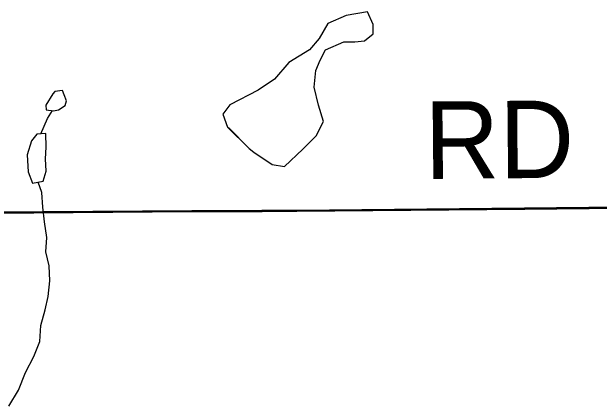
# Model space of a CAD drawing. Extents: x 0 to 34, y 0 to 22.
# Drawn here: x 24.4702 to 24.9014, y 12.5806 to 12.87 of the extents above; entities that cross this region are included whole.
import ezdxf

# ---------------------------------------------------------------- set-up
doc = ezdxf.new("R2010")
doc.units = 0
for name, color, linetype in [('GM_X_Corporation', 7, 'Continuous'), ('GM_X_County_Road', 7, 'Continuous'), ('GM_X_County_Road_Text', 7, 'Continuous'), ('GM_X_Minor_Lake', 7, 'Continuous'), ('GM_X_Minor_River', 7, 'Continuous')]:
    doc.layers.add(name, color=color, linetype=linetype)

msp = doc.modelspace()

# ---------------------------------------------------------------- linework, layer by layer
at = {"layer": 'GM_X_Corporation'}
for points in [[(25.33919, 12.72985), (25.3125, 12.72939), (25.28828, 12.729), (25.15404, 12.7277), (25.13367, 12.72762), (24.97571, 12.72705), (24.91727, 12.72656), (24.84644, 12.72583), (24.6793, 12.72429), (24.65383, 12.72414), (24.60225, 12.72396), (24.45681, 12.72289)], [(24.45681, 12.72289), (24.60225, 12.72396), (24.65383, 12.72414), (24.6793, 12.72429), (24.84644, 12.72583), (24.91727, 12.72656), (24.97571, 12.72705), (25.13367, 12.72762), (25.15404, 12.7277), (25.28828, 12.729), (25.3125, 12.72939), (25.33919, 12.72985)]]:
    msp.add_lwpolyline(points, dxfattribs=at)
at = {"layer": 'GM_X_County_Road'}
msp.add_lwpolyline([(24.33555, 12.72187), (24.36213, 12.72202), (24.3875, 12.72204), (24.40983, 12.72221), (24.4359, 12.72217), (24.45702, 12.72234), (24.60246, 12.7234), (24.65404, 12.72358), (24.6795, 12.72374), (24.84664, 12.72528), (24.91748, 12.72601), (24.97591, 12.7265), (25.13388, 12.72707)], dxfattribs=at)
at = {"layer": 'GM_X_Minor_Lake'}
for p, q in [((24.50038, 12.80986), (24.49515, 12.80148)), ((24.6285, 12.78543), (24.64452, 12.76963)), ((24.64452, 12.76963), (24.62929, 12.78507)), ((24.48143, 12.76497), (24.48214, 12.75252))]:
    msp.add_line(p, q, dxfattribs=at)
for points in [[(24.73117, 12.87003), (24.71567, 12.86725), (24.70209, 12.86146), (24.69574, 12.85042), (24.68862, 12.84202), (24.67355, 12.8328), (24.66305, 12.82059), (24.651, 12.81253), (24.63027, 12.80175), (24.62502, 12.79489), (24.6285, 12.78543)], [(24.64452, 12.76963), (24.64794, 12.767), (24.66126, 12.758), (24.67036, 12.75655), (24.68388, 12.76917), (24.69365, 12.7791), (24.69887, 12.78938), (24.69537, 12.80149), (24.69223, 12.81474), (24.69328, 12.82688), (24.69662, 12.8345), (24.70035, 12.84211), (24.71393, 12.8479), (24.72188, 12.84796), (24.72906, 12.84877), (24.73546, 12.85375), (24.7354, 12.86058), (24.73117, 12.87003), (24.71567, 12.86725), (24.70209, 12.86146), (24.69574, 12.85042), (24.68862, 12.84202), (24.67355, 12.8328), (24.66305, 12.82059), (24.651, 12.81253), (24.63027, 12.80175), (24.62502, 12.79489), (24.6285, 12.78543)], [(24.64452, 12.76963), (24.64794, 12.767), (24.66126, 12.758), (24.67036, 12.75655), (24.68388, 12.76917), (24.69365, 12.7791), (24.69887, 12.78938), (24.69537, 12.80149), (24.69223, 12.81474), (24.69328, 12.82688), (24.69662, 12.8345), (24.70035, 12.84211), (24.71393, 12.8479), (24.72188, 12.84796), (24.72906, 12.84877), (24.73546, 12.85375), (24.7354, 12.86058), (24.73117, 12.87003)], [(24.49515, 12.80148), (24.49555, 12.79807), (24.50086, 12.79735), (24.50464, 12.79814), (24.50953, 12.80121), (24.51027, 12.80463), (24.50872, 12.80917), (24.50756, 12.8122), (24.50188, 12.81139), (24.50038, 12.80986)], [(24.48214, 12.75252), (24.48538, 12.74414), (24.49331, 12.74572), (24.49553, 12.75294), (24.49508, 12.76204), (24.49539, 12.77076), (24.49531, 12.78062), (24.4885, 12.78019), (24.48476, 12.77523), (24.48143, 12.76497)]]:
    msp.add_lwpolyline(points, dxfattribs=at)
at = {"layer": 'GM_X_Minor_River'}
for points in [[(24.4915, 12.78038), (24.49636, 12.79168), (24.50013, 12.79745)], [(24.46811, 12.58056), (24.47521, 12.59237), (24.48041, 12.6053), (24.48637, 12.61711), (24.49083, 12.62814), (24.49149, 12.6399), (24.49481, 12.6513), (24.497, 12.66118), (24.49805, 12.67256), (24.49758, 12.68356), (24.49523, 12.69378), (24.49591, 12.7044), (24.4943, 12.71577), (24.49308, 12.72676), (24.49224, 12.73737), (24.48964, 12.74499)]]:
    msp.add_lwpolyline(points, dxfattribs=at)

# ---------------------------------------------------------------- texts
at = {"layer": 'GM_X_County_Road_Text'}
msp.add_text('RD', height=0.056818, rotation=0.4827, dxfattribs=at).set_placement((24.77336, 12.74732))

doc.saveas('drawing.dxf')
